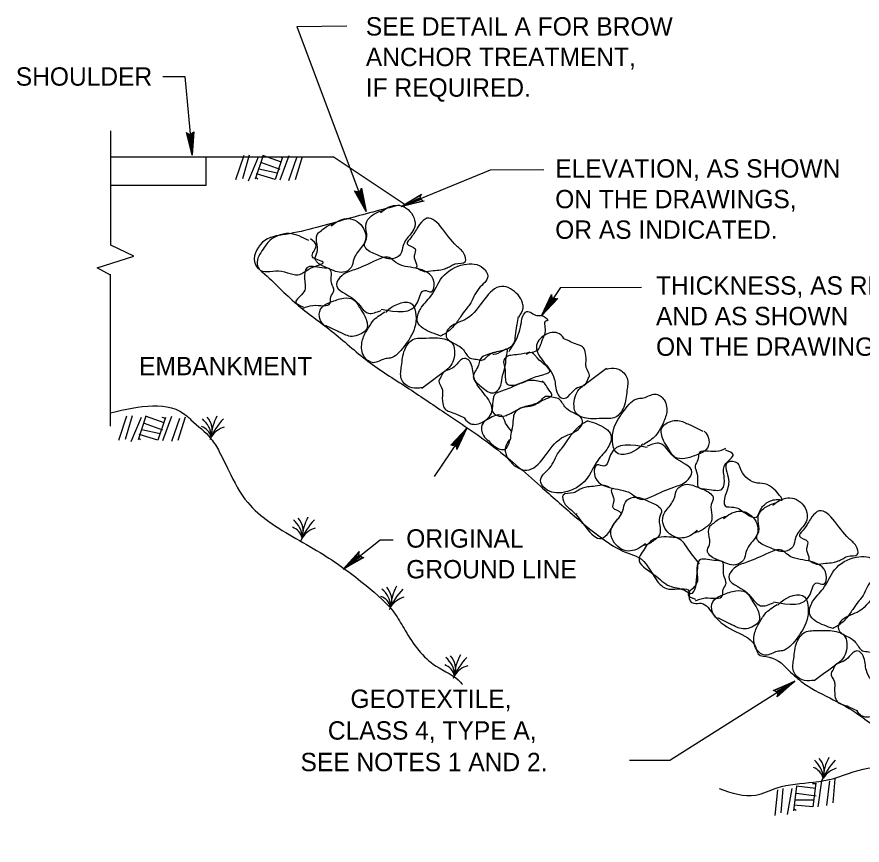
# Model space of a CAD drawing. Extents: x 5 to 910, y -47 to 547.
# Drawn here: x 398.4 to 524.8, y 136.5 to 260.3 of the extents above; entities that cross this region are included whole.
import ezdxf

# ---------------------------------------------------------------- set-up
doc = ezdxf.new("R2010")
doc.units = 0
for name, color, linetype in [('1', 7, 'Continuous'), ('2', 7, 'Continuous'), ('3', 7, 'Continuous')]:
    doc.layers.add(name, color=color, linetype=linetype)

msp = doc.modelspace()

# ---------------------------------------------------------------- linework, layer by layer
at = {"layer": '1'}
for p, q in [((432.31, 239.59), (431.1, 235.95)), ((433.13, 239.66), (432.13, 236.11)), ((434.48, 239.38), (432.95, 235.75)), ((435.21, 239.59), (434.02, 236.04)), ((437.96, 238.61), (435.17, 239.59)), ((438.12, 239.38), (437, 236.02)), ((438.17, 239.27), (437.64, 239.38)), ((439.03, 239.54), (437.71, 235.91)), ((440.22, 239.27), (439.01, 235.81)), ((441.07, 239.43), (440, 235.98)), ((437.75, 237.49), (435.01, 238.49)), ((437, 236.02), (434.21, 236.87)), ((437.32, 236.94), (434.57, 237.58)), ((434.41, 236.04), (434.16, 236.27)), ((414.78, 200.6), (413.57, 196.97)), ((415.61, 200.67), (414.6, 197.13)), ((416.96, 200.4), (415.42, 196.76)), ((417.69, 200.6), (416.5, 197.06)), ((420.43, 199.62), (417.64, 200.6)), ((420.59, 200.4), (419.47, 197.04)), ((420.64, 200.28), (420.11, 200.4)), ((421.51, 200.56), (420.18, 196.92)), ((422.7, 200.28), (421.49, 196.83)), ((423.55, 200.44), (422.47, 196.99)), ((419.79, 197.95), (417.05, 198.59)), ((420.23, 198.5), (417.48, 199.51)), ((416.89, 197.06), (416.64, 197.29)), ((419.47, 197.04), (416.68, 197.88)), ((517.9, 145.63), (517.37, 145.63)), ((517.85, 145.72), (517.44, 142.17)), ((518.72, 146.06), (518.17, 142.2)), ((519.93, 146.06), (519.48, 142.38)), ((520.73, 146.36), (520.39, 142.77)), ((512.11, 144.74), (511.72, 140.87)), ((512.93, 144.94), (512.61, 141.28)), ((514.28, 144.94), (513.57, 141.05)), ((514.97, 145.28), (514.53, 141.6)), ((517.85, 144.9), (514.92, 145.28)), ((517.9, 143.75), (514.99, 144.19)), ((517.55, 143.18), (514.76, 143.18)), ((517.44, 142.17), (514.56, 142.42)), ((514.9, 141.65), (514.63, 141.85))]:
    msp.add_line(p, q, dxfattribs=at)
at = {"layer": '2'}
for p, q in [((440.26, 258.92), (447.74, 258.99)), ((440.26, 258.92), (450.61, 231.24)), ((420.21, 251.42), (423.48, 251.42)), ((423.48, 251.42), (424.62, 239.64)), ((412.43, 239.43), (445.69, 239.43)), ((426.68, 235.15), (426.68, 239.45)), ((456.58, 232.15), (445.69, 239.43)), ((455.85, 231.97), (469.21, 237.46)), ((469.21, 237.46), (477.17, 237.49)), ((412.43, 235.17), (426.68, 235.17)), ((479.69, 219.85), (476.85, 215.61)), ((479.69, 219.85), (491.77, 219.89)), ((465.67, 198.84), (460.79, 191.57)), ((447.18, 177.75), (452.72, 182.12)), ((452.72, 182.12), (454.66, 182.12)), ((496.04, 149.16), (514.74, 160.98)), ((490.01, 149.14), (496.04, 149.16))]:
    msp.add_line(p, q, dxfattribs=at)
for points in [[(424.71, 242.98), (424.48, 242.84), (424.62, 239.64), (424.71, 242.98), (424.85, 243.16), (424.62, 239.64), (424.16, 242.79), (423.91, 242.91), (424.62, 239.64), (423.73, 243.07), (423.91, 242.91)], [(449.83, 234.49), (449.65, 234.3), (450.61, 231.24), (449.83, 234.49), (449.92, 234.72), (450.61, 231.24), (449.35, 234.17), (449.08, 234.21), (450.61, 231.24), (448.87, 234.33), (449.08, 234.21)], [(459.08, 232.84), (458.87, 233.02), (455.85, 231.97), (459.08, 232.84), (459.3, 232.77), (455.85, 231.97), (458.76, 233.34), (458.76, 233.6), (455.85, 231.97), (458.87, 233.82), (458.76, 233.6)], [(479.05, 218.15), (478.77, 218.18), (476.85, 215.61), (479.05, 218.15), (479.26, 218.2), (476.85, 215.61), (478.5, 218.36), (478.36, 218.59), (476.85, 215.61), (478.34, 218.82), (478.36, 218.59)], [(463.47, 196.3), (463.74, 196.28), (465.67, 198.84), (463.47, 196.3), (463.26, 196.26), (465.67, 198.84), (464.02, 196.1), (464.16, 195.87), (465.67, 198.84), (464.18, 195.64), (464.16, 195.87)], [(450.04, 179.49), (449.81, 179.6), (447.18, 177.75), (450.04, 179.49), (450.27, 179.46), (447.18, 177.75), (449.58, 179.85), (449.54, 180.11), (447.18, 177.75), (449.58, 180.36), (449.54, 180.11)], [(511.7, 159.56), (511.95, 159.42), (514.74, 160.98), (511.7, 159.56), (511.49, 159.58), (514.74, 160.98), (512.13, 159.13), (512.15, 158.87), (514.74, 160.98), (512.09, 158.65), (512.15, 158.87)]]:
    msp.add_lwpolyline(points, dxfattribs=at)
for centre, radius, start, end in [((423.69, 197.27), 3.81, 5.458, 50.1012), ((424.64, 198.48), 2.97, 341.9451, 42.0595), ((436.39, 193.34), 9.89, 136.0953, 157.8863), ((434.51, 197.19), 7.08, 151.1864, 177.3718), ((425.23, 196.95), 2.27, 14.3361, 70.4588), ((430.44, 195.53), 3.6, 106.7524, 146.5599), ((437.3, 182.17), 3.81, 5.458, 50.1012), ((438.25, 183.38), 2.97, 341.9451, 42.0595), ((450, 178.24), 9.89, 136.0953, 157.8863), ((448.12, 182.09), 7.08, 151.1864, 177.3718), ((438.85, 181.85), 2.27, 14.3361, 70.4588), ((444.05, 180.43), 3.6, 106.7524, 146.5599), ((450.52, 171.83), 3.81, 5.458, 50.1012), ((451.48, 173.04), 2.97, 341.9451, 42.0595), ((463.23, 167.9), 9.89, 136.0953, 157.8863), ((461.35, 171.75), 7.08, 151.1864, 177.3718), ((452.07, 171.51), 2.27, 14.3361, 70.4588), ((457.28, 170.09), 3.6, 106.7524, 146.5599), ((460.09, 161.58), 3.81, 5.458, 50.1012), ((461.04, 162.79), 2.97, 341.9451, 42.0595), ((472.79, 157.65), 9.89, 136.0953, 157.8863), ((470.91, 161.5), 7.08, 151.1864, 177.3718), ((461.63, 161.26), 2.27, 14.3361, 70.4588), ((466.84, 159.84), 3.6, 106.7524, 146.5599), ((515.2, 146.23), 3.81, 5.458, 50.1012), ((516.15, 147.44), 2.97, 341.9451, 42.0595), ((527.9, 142.29), 9.89, 136.0953, 157.8863), ((526.03, 146.15), 7.08, 151.1864, 177.3718), ((516.75, 145.91), 2.27, 14.3361, 70.4588), ((521.96, 144.49), 3.6, 106.7524, 146.5599)]:
    msp.add_arc(centre, radius, start, end, dxfattribs=at)
for points in [[(412.4, 201.13), (423.87, 200.6), (424.42, 200.08), (427.41, 197.24), (428.65, 195.3), (430.07, 192.46), (432.9, 187.68), (436.08, 184.84), (444.23, 179.9), (450.61, 175.28), (455.05, 170.86), (456.45, 168.55), (461.07, 163.24), (464.77, 160.77), (465.01, 160.48)], [(503.41, 144.9), (508.88, 143.93), (512.06, 145.01), (517.53, 145.88), (520.55, 146.43), (526.41, 148.03), (528.17, 148.03), (531.72, 148.72)]]:
    msp.add_spline(points, degree=3, dxfattribs=at)
at = {"layer": '3'}
for p, q in [((412.43, 226.18), (412.43, 243.3)), ((412.4, 199.12), (412.38, 221.86)), ((446.42, 213.26), (444.55, 214.19)), ((476.12, 205.94), (477.13, 205.68)), ((499.09, 199.3), (500.97, 198.36)), ((482.05, 186.05), (482.02, 185.85)), ((505.08, 169.49), (503.21, 170.43))]:
    msp.add_line(p, q, dxfattribs=at)
msp.add_lwpolyline([(412.38, 221.72), (410.41, 222.82), (415.88, 224.54), (412.43, 226.18)], dxfattribs=at)
for points in [[(455.6, 232.18), (447.66, 230.07), (438.55, 227.81), (435.12, 226.62), (434.05, 223.3), (435.12, 222.13), (440.2, 217.4), (445.42, 213.35), (450.86, 208.86), (456.67, 204.95), (462.35, 201.15), (469.35, 196.3), (476.67, 190.15), (481.77, 185.67), (486.39, 181.98), (489.82, 180.11), (491.36, 179.49), (493.97, 176.19), (495.86, 174.75), (498.93, 174.39), (499.05, 172.99), (499.64, 172.62), (500.72, 172.62), (502.61, 170.86), (505.93, 168.37), (508.88, 166.01), (509.25, 165.05), (510.9, 164.57), (514.1, 162.33), (516.23, 160.54), (520.48, 158.19), (524.17, 156.04), (527, 154.05), (529.73, 151.9), (531.14, 149.31), (533.27, 148.94), (535.17, 147.41), (536.59, 145.63), (538.95, 143.27), (544.99, 138.05), (546.88, 136.98), (548.9, 136.52), (553.27, 137.46), (556.72, 138.54), (560.63, 140.07), (566.42, 143.16), (567.25, 144.8)], [(452.76, 231.01), (453.24, 231.42), (455.64, 232.13), (457.75, 230.32), (457.86, 228.84), (457.25, 227.83), (456.15, 226.14), (455.76, 224.83), (454.57, 224.15), (452.26, 224.74), (450.57, 225.73), (450.36, 226.14), (450.66, 227.12), (450.57, 228.75), (450.86, 230.03), (450.95, 230.14), (452.35, 231.12), (453.2, 231.42)], [(445.39, 229.02), (445.88, 229.43), (448.28, 230.14), (450.38, 228.33), (450.47, 226.82), (449.88, 225.84), (448.78, 224.12), (448.37, 222.84), (447.18, 222.13), (444.89, 222.75), (443.2, 223.74), (442.99, 224.12), (443.29, 225.13), (443.2, 226.73), (443.47, 228.04), (443.59, 228.13), (444.98, 229.13), (445.81, 229.41)], [(458.3, 222.73), (459.3, 222.27), (460.65, 222.39), (461.78, 222.5), (462.55, 222.73), (463.22, 223.05), (463.9, 223.39), (465.46, 223.74), (465.23, 224.95), (464.13, 226.09), (459.42, 230.1), (458.39, 228.97), (457.29, 227.3), (456.74, 226.41), (457.96, 225.63), (457.84, 224.74), (457.84, 224.17), (458.18, 223.05), (458.07, 222.73)], [(442.03, 226.87), (439.1, 227.92), (435.92, 226.59), (435.37, 225.82), (434.32, 223.67), (434.6, 222.61), (437.52, 222.34), (440.7, 221.81), (442.03, 222.61), (444.18, 223.67), (442.58, 224.47), (443.13, 226.07), (442.31, 227.14)], [(452.85, 216.62), (458.34, 217.72), (459.35, 219.43), (460.36, 219.23), (460.77, 220.62), (458.07, 222.73), (455.05, 223.62), (454.07, 224.33), (452.17, 223.94), (448.87, 222.52), (446.97, 221.63), (446.17, 220.33), (448.87, 218.02), (450.95, 216.02), (452.85, 216.44)], [(441.21, 216.76), (442.65, 217.19), (445.23, 217.53), (445.35, 218.45), (445.78, 219.34), (445.44, 220.55), (445.23, 222.57), (444, 222.8), (441.76, 222.8), (441.41, 221.13), (441.32, 219.23), (440.09, 217.65), (441.21, 216.99)], [(461.78, 212.59), (460.43, 213.1), (458.3, 214.77), (458.73, 216.64), (460.29, 218.56), (462, 221.4), (465.28, 223.3), (468.14, 222.75), (468.82, 221.54), (467.47, 219.71), (466.08, 217.28), (465.55, 216.62), (464.73, 215.48), (463.7, 214.06), (462.46, 213), (461.73, 212.59)], [(473.44, 215.43), (474.08, 216.76), (474.02, 217.53), (473.33, 218.75), (470.88, 220.03), (468.32, 218.13), (465.67, 215.2), (463.15, 213.9), (462.58, 213.03), (462.6, 212.5), (464.02, 211.38), (465.16, 210.53), (466.17, 209.3), (467.13, 209.12), (467.88, 208.98), (469.23, 209.96), (469.94, 210.21), (471.8, 210.76), (472.67, 211.43), (472.92, 212.34), (473.08, 213.76), (473.19, 214.33), (473.38, 215.52)], [(444.34, 214.17), (444.11, 214.45), (443.63, 215.48), (444.02, 216.92), (445.3, 217.65), (447.23, 218.27), (448.73, 218.04), (449.7, 216.76), (450.43, 215.57), (450.75, 214.61), (450.75, 213.81), (450.11, 213.1), (448.03, 212.59), (447.16, 212.94), (446.42, 213.26)], [(453.54, 216.12), (454.02, 216.6), (457.52, 217.35), (458.07, 215.7), (457.86, 213.81), (456.24, 210.97), (454.2, 209.3), (453.4, 209.18), (451.71, 208.61), (450.34, 209.5), (449.99, 211.59), (450.66, 213.33), (450.73, 213.44), (451.59, 214.79), (453.4, 216.21)], [(471.98, 210.28), (472.92, 211.79), (473.83, 214.63), (474.04, 215.57), (474.63, 216.25), (476.12, 215.68), (477.15, 215.57), (477.72, 214.88), (477.61, 214.88), (477.38, 213.39), (477.04, 212.23), (476.69, 211.33), (475.89, 210.28), (474.63, 209.94), (474.75, 209.94)], [(459.03, 204.86), (458.6, 204.81), (457.15, 204.93), (455.87, 206.26), (455.9, 208.11), (456.38, 210.56), (457.61, 212.07), (459.58, 212.3), (461.34, 212.32), (462.58, 212.09), (463.45, 211.59), (463.83, 210.44), (463.03, 207.88), (462.14, 207.15), (458.94, 204.77)], [(480.19, 212.27), (479.26, 213.05), (478.66, 213.14), (477.58, 212.89), (476.1, 211.24), (477.04, 208.89), (478.75, 206.21), (479.23, 204.01), (479.78, 203.37), (480.19, 203.28), (481.36, 204.15), (482.23, 204.88), (483.42, 205.41), (483.76, 206.1), (484.01, 206.64), (483.53, 207.9), (483.49, 208.5), (483.44, 210.03), (483.1, 210.85), (482.46, 211.24), (481.38, 211.63), (480.95, 211.86), (480.1, 212.23)], [(469.58, 210.05), (467.63, 209.05), (467.4, 208.22), (466.63, 206.51), (467.86, 205.02), (469.69, 204.11), (470.63, 204.91), (470.97, 206.39), (471.43, 208.11), (471.64, 209.82), (471.75, 210.51), (469.69, 209.82), (469.58, 209.82)], [(475.09, 210.17), (473.38, 209.82), (472.23, 209.71), (471.64, 209.5), (471.2, 208.93), (471.32, 207.99), (471.43, 206.96), (471.75, 205.36), (472.46, 205.25), (474.4, 205.82), (476.35, 206.62), (478.07, 207.31), (476.24, 209.28), (475.89, 209.71), (475.32, 210.17)], [(465.34, 200.26), (466.26, 199.48), (466.85, 199.39), (467.93, 199.67), (469.42, 201.29), (468.48, 203.67), (466.76, 206.32), (466.28, 208.52), (465.73, 209.16), (465.34, 209.25), (464.18, 208.41), (463.29, 207.67), (462.12, 207.15), (461.78, 206.46), (461.5, 205.91), (461.98, 204.65), (462.03, 204.06), (462.07, 202.5), (462.42, 201.68), (463.06, 201.29), (464.13, 200.93), (464.57, 200.7), (465.44, 200.31)], [(486.48, 207.67), (486.92, 207.74), (488.36, 207.63), (489.64, 206.28), (489.62, 204.45), (489.14, 201.98), (487.9, 200.47), (485.94, 200.26), (484.17, 200.22), (482.94, 200.47), (482.07, 200.97), (481.7, 202.11), (482.48, 204.65), (483.37, 205.41), (486.58, 207.79)], [(476.19, 205.87), (475.39, 205.96), (473.33, 205.39), (471.27, 204.49), (469.81, 203.81), (469.53, 202.39), (469.53, 201.25), (470.93, 200.58), (471.73, 200.79), (473.97, 201.89), (475.53, 202.23), (477.61, 203.26), (478.39, 203.69), (477.95, 204.56), (477.38, 205.41), (476.94, 205.89)], [(472.07, 197.13), (471.43, 195.78), (471.5, 195.02), (472.19, 193.81), (474.63, 192.53), (477.2, 194.43), (479.85, 197.36), (482.37, 198.66), (482.94, 199.53), (482.94, 200.03), (481.52, 201.15), (480.35, 202), (479.35, 203.24), (478.39, 203.44), (477.63, 203.58), (476.28, 202.6), (475.57, 202.34), (473.72, 201.79), (472.85, 201.13), (472.6, 200.19), (472.44, 198.8), (472.32, 198.2), (472.14, 197.04)], [(491.98, 196.44), (491.5, 195.94), (487.99, 195.21), (487.45, 196.83), (487.65, 198.75), (489.28, 201.57), (491.31, 203.26), (492.11, 203.35), (493.81, 203.92), (495.18, 203.05), (495.52, 200.97), (494.86, 199.23), (494.79, 199.09), (493.92, 197.74), (492.11, 196.35)], [(472.41, 198.34), (471.48, 199.58), (470.84, 200.7), (468.94, 200.22), (468, 199.44), (468.16, 197.7), (468.94, 196.9), (470.36, 195.78), (471.32, 195.64), (472.12, 197.06)], [(483.76, 199.94), (485.09, 199.46), (487.22, 197.77), (486.78, 195.91), (485.25, 193.99), (483.53, 191.16), (480.24, 189.23), (477.38, 189.78), (476.69, 191), (478.04, 192.85), (479.44, 195.25), (479.96, 195.91), (480.79, 197.08), (481.84, 198.48), (483.08, 199.55), (483.79, 199.96)], [(501.17, 198.39), (501.4, 198.11), (501.88, 197.06), (501.49, 195.62), (500.21, 194.89), (498.29, 194.27), (496.78, 194.5), (495.82, 195.78), (495.09, 196.99), (494.77, 197.95), (494.77, 198.73), (495.41, 199.46), (497.49, 199.94), (498.36, 199.62), (499.09, 199.3)], [(492.66, 195.91), (487.17, 194.84), (486.16, 193.12), (485.16, 193.33), (484.75, 191.91), (487.45, 189.83), (490.47, 188.91), (491.45, 188.23), (493.35, 188.62), (496.64, 190.01), (498.54, 190.9), (499.34, 192.23), (496.64, 194.52), (494.56, 196.53), (492.66, 196.12)], [(504.38, 195.78), (502.93, 195.32), (500.35, 195), (500.23, 194.08), (499.8, 193.19), (500.14, 191.96), (500.35, 189.94), (501.58, 189.71), (503.83, 189.71), (504.17, 191.41), (504.26, 193.31), (505.5, 194.89), (504.38, 195.55)], [(512.73, 188.43), (510.19, 190.49), (508.75, 190.68), (506.55, 192.87), (506.23, 193.51), (504.63, 193.67), (504.81, 191.13), (504.33, 188.75), (504.33, 187.18), (505.59, 187.01), (507.17, 186.21), (509.09, 185.6), (509.39, 186.21), (510.32, 187.5), (511.93, 188.14), (512.38, 188.14)], [(487.22, 189.83), (486.21, 190.26), (484.88, 190.15), (483.76, 190.03), (482.96, 189.83), (482.3, 189.49), (481.63, 189.14), (480.08, 188.82), (480.28, 187.59), (481.41, 186.47), (486.1, 182.44), (487.13, 183.56), (488.22, 185.23), (488.77, 186.12), (487.56, 186.9), (487.67, 187.82), (487.67, 188.36), (487.33, 189.49), (487.45, 189.83)], [(500.12, 183.54), (499.64, 183.1), (497.24, 182.42), (495.13, 184.2), (495.04, 185.71), (495.64, 186.72), (496.73, 188.41), (497.15, 189.69), (498.34, 190.4), (500.62, 189.81), (502.32, 188.82), (502.52, 188.41), (502.23, 187.4), (502.32, 185.8), (502.04, 184.52), (501.93, 184.41), (500.53, 183.42), (499.71, 183.13)], [(492.39, 181.59), (491.91, 181.18), (489.5, 180.47), (487.4, 182.28), (487.29, 183.79), (487.9, 184.77), (489, 186.49), (489.39, 187.77), (490.58, 188.48), (492.89, 187.86), (494.58, 186.88), (494.79, 186.49), (494.49, 185.48), (494.58, 183.88), (494.29, 182.58), (494.19, 182.48), (492.8, 181.48), (491.95, 181.2)], [(511.42, 187.24), (511.9, 187.66), (514.31, 188.36), (516.41, 186.56), (516.52, 185.07), (515.91, 184.06), (514.81, 182.37), (514.42, 181.07), (513.23, 180.38), (510.92, 180.97), (509.23, 181.96), (509.02, 182.37), (509.32, 183.35), (509.23, 184.98), (509.52, 186.26), (509.61, 186.37), (511.01, 187.36), (511.86, 187.66)], [(512.38, 188.14), (512.82, 188.07), (512.68, 188.46)], [(516.96, 178.96), (517.97, 178.5), (519.32, 178.62), (520.44, 178.73), (521.21, 178.96), (521.88, 179.28), (522.56, 179.63), (524.12, 179.97), (523.89, 181.18), (522.79, 182.32), (518.08, 186.33), (517.05, 185.21), (515.95, 183.54), (515.4, 182.65), (516.62, 181.87), (516.5, 180.97), (516.5, 180.4), (516.84, 179.28), (516.73, 178.96)], [(504.06, 185.25), (504.54, 185.67), (506.94, 186.37), (509.04, 184.57), (509.13, 183.06), (508.54, 182.07), (507.44, 180.36), (507.03, 179.08), (505.84, 178.37), (503.55, 178.98), (501.86, 179.97), (501.65, 180.36), (501.95, 181.36), (501.86, 182.97), (502.13, 184.27), (502.25, 184.36), (503.64, 185.37), (504.47, 185.64)], [(500.46, 178.53), (498.86, 180.59), (497.28, 182.32), (496.35, 182.51), (493.33, 182.03), (491.91, 180.27), (491.43, 179.33), (493.65, 176.95), (496, 175.21), (498.22, 174.57), (499.18, 174.11), (500.12, 177.11), (500.28, 178.53)], [(511.51, 172.85), (517, 173.95), (518.01, 175.67), (519.02, 175.46), (519.43, 176.86), (516.73, 178.96), (513.71, 179.85), (512.73, 180.56), (510.83, 180.17), (507.53, 178.76), (505.63, 177.86), (504.83, 176.56), (507.53, 174.25), (509.61, 172.26), (511.51, 172.67)], [(520.44, 168.83), (519.09, 169.33), (516.96, 171), (517.39, 172.88), (518.95, 174.8), (520.67, 177.63), (523.94, 179.53), (526.8, 178.98), (527.48, 177.77), (526.13, 175.94), (524.74, 173.52), (524.21, 172.85), (523.39, 171.71), (522.36, 170.29), (521.12, 169.24), (520.39, 168.83)], [(499.87, 172.99), (501.31, 173.42), (503.9, 173.77), (504.01, 174.68), (504.44, 175.58), (504.1, 176.79), (503.9, 178.8), (502.66, 179.03), (500.42, 179.03), (500.07, 177.36), (499.98, 175.46), (498.75, 173.88), (499.87, 173.22)], [(532.1, 171.66), (532.75, 172.99), (532.68, 173.77), (531.99, 174.98), (529.54, 176.26), (526.98, 174.36), (524.33, 171.43), (521.81, 170.13), (521.24, 169.26), (521.26, 168.73), (522.68, 167.61), (523.82, 166.77), (524.83, 165.53), (525.79, 165.35), (526.55, 165.21), (527.89, 166.2), (528.6, 166.45), (530.46, 167), (531.33, 167.66), (531.58, 168.57), (531.74, 169.99), (531.85, 170.57), (532.04, 171.75)], [(503, 170.4), (502.77, 170.68), (502.29, 171.71), (502.68, 173.15), (503.96, 173.88), (505.89, 174.5), (507.4, 174.27), (508.36, 172.99), (509.09, 171.8), (509.41, 170.84), (509.41, 170.04), (508.77, 169.33), (506.69, 168.83), (505.82, 169.17), (505.08, 169.49)], [(512.2, 172.35), (512.68, 172.83), (516.18, 173.59), (516.73, 171.94), (516.52, 170.04), (514.9, 167.2), (512.86, 165.53), (512.06, 165.42), (510.37, 164.85), (509, 165.74), (508.65, 167.82), (509.32, 169.56), (509.39, 169.67), (510.26, 171.02), (512.06, 172.44)], [(517.69, 161.09), (517.26, 161.05), (515.82, 161.16), (514.53, 162.49), (514.56, 164.34), (515.04, 166.79), (516.27, 168.3), (518.24, 168.53), (520, 168.55), (521.24, 168.32), (522.11, 167.82), (522.5, 166.68), (521.69, 164.11), (520.8, 163.38), (517.6, 161)], [(524.01, 156.49), (524.92, 155.72), (525.52, 155.63), (526.59, 155.9), (528.08, 157.52), (527.14, 159.9), (525.42, 162.56), (524.94, 164.75), (524.39, 165.39), (524.01, 165.49), (522.84, 164.64), (521.95, 163.91), (520.78, 163.38), (520.44, 162.69), (520.16, 162.15), (520.64, 160.89), (520.69, 160.29), (520.73, 158.74), (521.08, 157.91), (521.72, 157.52), (522.79, 157.16), (523.23, 156.93), (524.1, 156.54)]]:
    msp.add_spline(points, degree=3, dxfattribs=at)

# ---------------------------------------------------------------- texts
at = {"layer": '2'}
for s, p in [('GEOTEXTILE,', (448.27, 156.97)), ('CLASS 4, TYPE A,', (444.89, 152.23)), ('SEE NOTES 1 AND 2.', (440.8, 147.51))]:
    msp.add_text(s, height=2.7454, dxfattribs=at).set_placement(p)
at = {"layer": '3'}
for s, height, p in [('SEE DETAIL A FOR BROW', 2.7454, (450.57, 257.55)), ('ANCHOR TREATMENT,', 2.7454, (450.57, 252.97)), ('SHOULDER', 2.745, (398.22, 250.05)), ('IF REQUIRED.', 2.7454, (450.57, 248.4)), ('ELEVATION, AS SHOWN', 2.7454, (478.89, 236.3)), ('ON THE DRAWINGS,', 2.7454, (478.89, 231.72)), ('OR AS INDICATED.', 2.7454, (478.89, 227.14)), ('THICKNESS, AS REQUIRED,', 2.7454, (493.97, 218.79)), ('AND AS SHOWN', 2.7454, (493.97, 214.22)), ('ON THE DRAWINGS.', 2.7454, (493.97, 209.64)), ('EMBANKMENT', 2.745, (416.66, 206.74)), ('ORIGINAL', 2.745, (456.61, 180.95)), ('GROUND LINE', 2.7454, (456.61, 176.35))]:
    msp.add_text(s, height=height, dxfattribs=at).set_placement(p)

doc.saveas('drawing.dxf')
